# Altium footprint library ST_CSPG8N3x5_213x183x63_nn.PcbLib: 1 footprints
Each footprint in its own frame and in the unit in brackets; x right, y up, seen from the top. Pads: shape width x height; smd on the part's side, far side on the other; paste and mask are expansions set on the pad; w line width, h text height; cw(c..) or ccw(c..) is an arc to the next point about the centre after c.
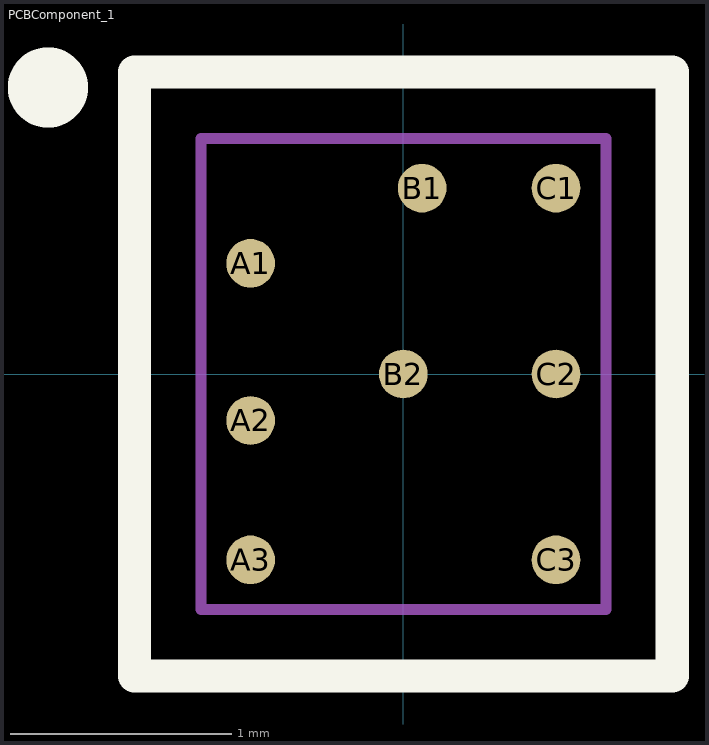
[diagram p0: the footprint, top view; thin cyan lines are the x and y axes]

## PCBComponent_1 [mm]
pads (8):
  round 0.22 smd paste+0 mask+0.05: A1(-0.69,0.5) A2(-0.69,-0.21) A3(-0.69,-0.84) B1(0.085,0.84) B2(0,0) C1(0.69,0.84) C2(0.69,0) C3(0.69,-0.84)
Top Overlay:
  circle w0.254: c-1.606,1.295 r0.054
  lines w0.15: -1.215,-1.365 1.215,-1.365 1.215,1.365 -1.215,1.365 -1.215,-1.365
Top Paste:
  rectangle: -0.025,0.73 0.195,0.95
  rectangle: 0.58,0.73 0.8,0.95
  rectangle: -0.8,0.39 -0.58,0.61
  rectangle: -0.11,-0.11 0.11,0.11
  rectangle: 0.58,-0.11 0.8,0.11
  rectangle: -0.8,-0.32 -0.58,-0.1
  rectangle: -0.8,-0.95 -0.58,-0.73
  rectangle: 0.58,-0.95 0.8,-0.73
Mechanical 3:
  lines w0.05: -0.915,-1.065 -0.915,1.065 0.915,1.065 0.915,-1.065 -0.915,-1.065
3D body "CSPG_8_Bumps_2-13x1-83x0-63_color.STEP": height 0.63, standoff -0.01, extent -0.915,-1.069 0.915,1.061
